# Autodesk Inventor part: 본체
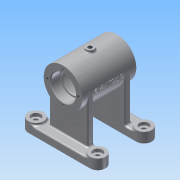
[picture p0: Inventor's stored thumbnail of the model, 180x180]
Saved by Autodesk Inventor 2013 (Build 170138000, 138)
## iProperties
Created: 2015-11
Part Number: 본체
Material: 알루미늄 6061
Document SubType Name: Modeling
Designer: Administrator
Density: 2.71 g/cm^3
Mass: 342.849 g
Surface Area: 451.522 cm^2
Volume: 126.513 cm^3
Author: Administrator
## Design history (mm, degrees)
sketch "스케치1"
  geometry: L1 (-40, 40)-(40, 40); L2 (40, -40)-(-40, -40); L3 (50, -30)-(-50, -30); L4 (50, 30)-(-50, 30); L5 (-40, 20)-(40, 20); L6 (-40, -20)-(40, -20); L7 (0, 40)-(0, -40); L8 (-8, 40)-(-8, -40); L9 (8, 40)-(8, -40); L10 (-40, 40)-(-40, 20); L11 (40, 40)-(40, 20); L12 (40, -20)-(40, -40); L13 (-40, -20)-(-40, -40); L14 (-40, 40)-(-40, 20); L15 (40, 20)-(40, 40); A1 r 10 centre (-40, 30) between (-40, 20) and (-50, 30); A2 r 10 centre (40, 30) between (40, 20) and (50, 30); A3 r 10 centre (40, -30) between (40, -20) and (50, -30); A4 r 10 centre (-40, -30) between (-40, -20) and (-50, -30); 3 further points
  constraints: 30 end point, 8 point on circle, 8 point on line, 4 centre point, 4 tangent, 3 midpoint, 3 perpendicular, 1 horizontal, 1 horizontal alignment, 1 parallel, 1 vertical alignment
  dimensions: "d9" = 10 distance between parallel lines of L4 L1; "d10" = 10 distance between parallel lines of L2 L3; "d11" = 20 diameter of A1; "d12" = 20 diameter of A2; "d13" = 20 diameter of A3; "d14" = 20 diameter of A4; "d16" = 8 distance between parallel lines of L8 L7; "d17" = 8 distance between parallel lines of L7 L9; "d18" = 70 distance between parallel lines of L1 L3; "d19" = 40 distance from line of point (0, 0) L1; "d20" = 8 distance from line of point (0, 0) L9; "d21" = 42 distance from line of L4.start L9; "d22" = 42 distance from line of L3.start L9; "d23" = 32 distance from line of L1.end L9; "d24" = 32 distance from line of L2.start L9; "d25" = 48 distance from line of L1.start L9; "d26" = 48 distance from line of A1.centre L9; "d27" = 48 distance from line of L6.start L9; "d28" = 48 distance from line of L2.end L9; "d29" = 58 distance from line of point (-50, 0) L9
extrude "돌출1" new body sketch "스케치1" distance "d30" = 13; taper "d31" = 0 deg
extrude "돌출2" join sketch "스케치1" distance "d32" = 10; taper "d33" = 0 deg
hole "구멍1" diameter "d38" = 6; stored, may be unused: countersink angle "d42" = 82 deg, drill point angle "d44" = 0 deg; dims "d36" = 10, "d37" = 10, "d39" = 6, "d40" = 12, "d41" = 4, "d43" = 8
hole "구멍2" diameter "d47" = 6; stored, may be unused: countersink angle "d51" = 82 deg, drill point angle "d53" = 0 deg; dims "d45" = 10, "d46" = 10, "d48" = 6, "d49" = 12, "d50" = 4, "d52" = 8
hole "구멍3" diameter "d56" = 6; stored, may be unused: countersink angle "d60" = 82 deg, drill point angle "d62" = 0 deg; dims "d54" = 10, "d55" = 10, "d57" = 6, "d58" = 12, "d59" = 4, "d61" = 8
hole "구멍4" diameter "d65" = 6; stored, may be unused: countersink angle "d69" = 82 deg, drill point angle "d71" = 0 deg; dims "d63" = 10, "d64" = 10, "d66" = 6, "d67" = 12, "d68" = 4, "d70" = 8
chamfer "모따기1" distance "d72" = 0.3; stored, may be unused: second distance "d73" = 2, angle "d74" = 45 deg
sketch "스케치2"
  geometry: 1 further point
sketch "스케치3"
  geometry: L1 (40, 0)-(-40, 0) reference; C1 r 25 at (0, 68); 2 further points
  constraints: 1 centre point, 1 midpoint, 1 vertical alignment
  dimensions: "d75" = 50 diameter of C1; "d76" = 68 distance from line of C1.centre L1
extrude "돌출4" join sketch "스케치3" stored distance "d77" = 70; taper "d78" = 0 deg
node "작업 평면2"
hole "구멍5" diameter "d85" = 28; stored, may be unused: countersink angle "d89" = 82 deg, drill point angle "d91" = 0 deg; dims "d83" = 10, "d84" = 10, "d86" = 6, "d87" = 32, "d88" = 12, "d90" = 2
hole "구멍6" diameter "d94" = 28; stored, may be unused: countersink angle "d98" = 82 deg, drill point angle "d100" = 0 deg; dims "d92" = 10, "d93" = 10, "d95" = 6, "d96" = 32, "d97" = 12, "d99" = 2
chamfer "모따기2" distance "d103" = 1; stored, may be unused: second distance "d104" = 2, angle "d105" = 45 deg
node "작업 평면3"
sketch "스케치5"
  geometry: L1 (-40, -40)-(40, -40) reference; L2 (40, -20)-(-40, -20) reference; L3 (-25, -35)-(25, -35) reference; C1 r 5 at (0, 0); A1 r 10 centre (-40, -30) between (-40, -40) and (-40, -20) reference; A2 r 10 centre (40, -30) between (40, -20) and (40, -40) reference; 1 further point
  constraints: 1 centre point, 1 coincident
  dimensions: "d107" = 10 diameter of C1
  node "투영된 루프2"
sketch "스케치6"
  geometry: 1 further point
extrude "돌출6" join sketch "스케치5" distance "d108" = 7; taper "d109" = 0 deg
hole "구멍7" diameter "d112" = 5.188; stored, may be unused: countersink angle "d116" = 82 deg, drill point angle "d118" = 0 deg; dims "d110" = 10, "d111" = 10, "d113" = 20, "d114" = 12, "d115" = 4, "d117" = 30
fillet "모깎기3" dims "d119" = 2
sketch "스케치7"
  geometry: L1 (-40, 68)-(40, 68) reference; C1 r 25 at (0, 0) reference; 2 further points
  dimensions: "d120" = 68 distance from line of point (-20, 0) L1; "d121" = 20 distance of point (-20, 0) C1.centre
hole "구멍8" sketch "스케치7" at (-20, 0) diameter "d122" = 3.242; stored, may be unused: countersink angle "d126" = 82 deg, drill point angle "d128" = 118 deg; dims "d123" = 8, "d124" = 12, "d125" = 4, "d127" = 10
node "작업 평면4"
sketch "스케치8"
  geometry: 1 further point
sketch "스케치9"
  geometry: L1 (80, -40)-(0, -40) reference; L2 (0, -60)-(80, -60) reference; L3 (80, -40)-(0, -40) reference; L4 (80, 0)-(0, 0) reference; L5 (0, 20)-(80, 20) reference; L6 (65, 8)-(15, 8); L7 (15, 8)-(15, 0); L8 (15, 0)-(65, 0); L9 (65, 0)-(65, 8); C1 r 3 at (80, -50) reference; C2 r 3 at (0, -50) reference; C3 r 3 at (80, 10) reference; C4 r 3 at (0, 10) reference; A1 r 10 centre (0, -50) between (0, -40) and (0, -60) reference; A2 r 10 centre (80, -50) between (80, -60) and (80, -40) reference; A3 r 10 centre (80, 10) between (80, 0) and (80, 20) reference; A4 r 10 centre (0, 10) between (0, 20) and (0, 0) reference; 3 further points
  constraints: 8 end point, 2 midpoint, 2 parallel, 1 coincident, 1 horizontal, 1 perpendicular
  dimensions: "d133" = 8 distance between parallel lines of L6 L8; "d135" = 50 distance between parallel lines of L7 L9; "d136" = 8 distance between parallel lines of L6 L4
  node "투영된 루프3"
  node "투영된 루프4"
extrude "돌출8" join sketch "스케치9" distance "d139" = 58; taper "d140" = 0 deg
fillet "모깎기2" dims "d102" = 0.3
sketch "스케치10"
  geometry: 1 further point
fillet "모깎기4" dims "d141" = 2
hole "구멍9" diameter "d144" = 28; stored, may be unused: countersink angle "d148" = 82 deg, drill point angle "d150" = 0 deg; dims "d142" = 10, "d143" = 10, "d145" = 8, "d146" = 32, "d147" = 12, "d149" = 2
hole "구멍10" diameter "d153" = 28; stored, may be unused: countersink angle "d157" = 82 deg, drill point angle "d159" = 0 deg; dims "d151" = 10, "d152" = 10, "d154" = 8, "d155" = 32, "d156" = 12, "d158" = 2
sketch "스케치4"
  geometry: C1 r 25 at (0, 68) reference; C2 r 21 at (0, 68); 1 further point
  constraints: 1 centre point, 1 coincident
  dimensions: "d80" = 42 diameter of C2
extrude "돌출5" cut sketch "스케치4" distance "d81" = 42; taper "d82" = 0 deg
hole "구멍11" diameter "d162" = 3.242; stored, may be unused: countersink angle "d166" = 82 deg, drill point angle "d168" = 118 deg; dims "d160" = 10, "d161" = 10, "d163" = 8, "d164" = 32, "d165" = 12, "d167" = 10
hole "구멍12" diameter "d171" = 3.242; stored, may be unused: countersink angle "d175" = 82 deg, drill point angle "d177" = 118 deg; dims "d169" = 10, "d170" = 10, "d172" = 8, "d173" = 32, "d174" = 12, "d176" = 10
hole "구멍13" diameter "d180" = 3.242; stored, may be unused: countersink angle "d184" = 82 deg, drill point angle "d186" = 118 deg; dims "d178" = 10, "d179" = 10, "d181" = 8, "d182" = 32, "d183" = 12, "d185" = 10
hole "구멍14" diameter "d189" = 3.242; stored, may be unused: countersink angle "d193" = 82 deg, drill point angle "d195" = 118 deg; dims "d187" = 10, "d188" = 10, "d190" = 8, "d191" = 32, "d192" = 12, "d194" = 10
node "작업 평면6"
sketch "스케치11"
  geometry: L1 (-19.887, 70.814)-(19.887, 70.814); L2 (19.887, 70.814)-(19.887, 65.186); L3 (19.887, 65.186)-(-19.887, 65.186); L4 (-19.887, 65.186)-(-19.887, 70.814); L5 (-35, 93)-(-35, 43) reference; L6 (35, 93)-(-35, 93) reference; 4 further points
  constraints: 2 midpoint, 1 horizontal alignment, 1 vertical alignment, 2 other
  dimensions: "d197" = 35 distance from line of L5 point (0, 68); "d198" = 25 distance from line of L6 point (0, 68)
feature "엠보싱1" sketch "스케치11" dims "d26" = 48, "d199" = 0.5, "d200" = 0
fillet "모깎기5" dims "d201" = 2
fillet "모깎기6" dims "d202" = 2
node "솔리드1"
mirror "대칭1"
pattern_circular "원형 패턴1" dims angle "d130" = 360 deg
mirror "대칭2"
mirror "대칭4"
node "작업 평면1"
node "투영된 루프1"
node "작업 평면5"
other parameters: "d79" = 21, "d106" = 96, "d196" = -25
